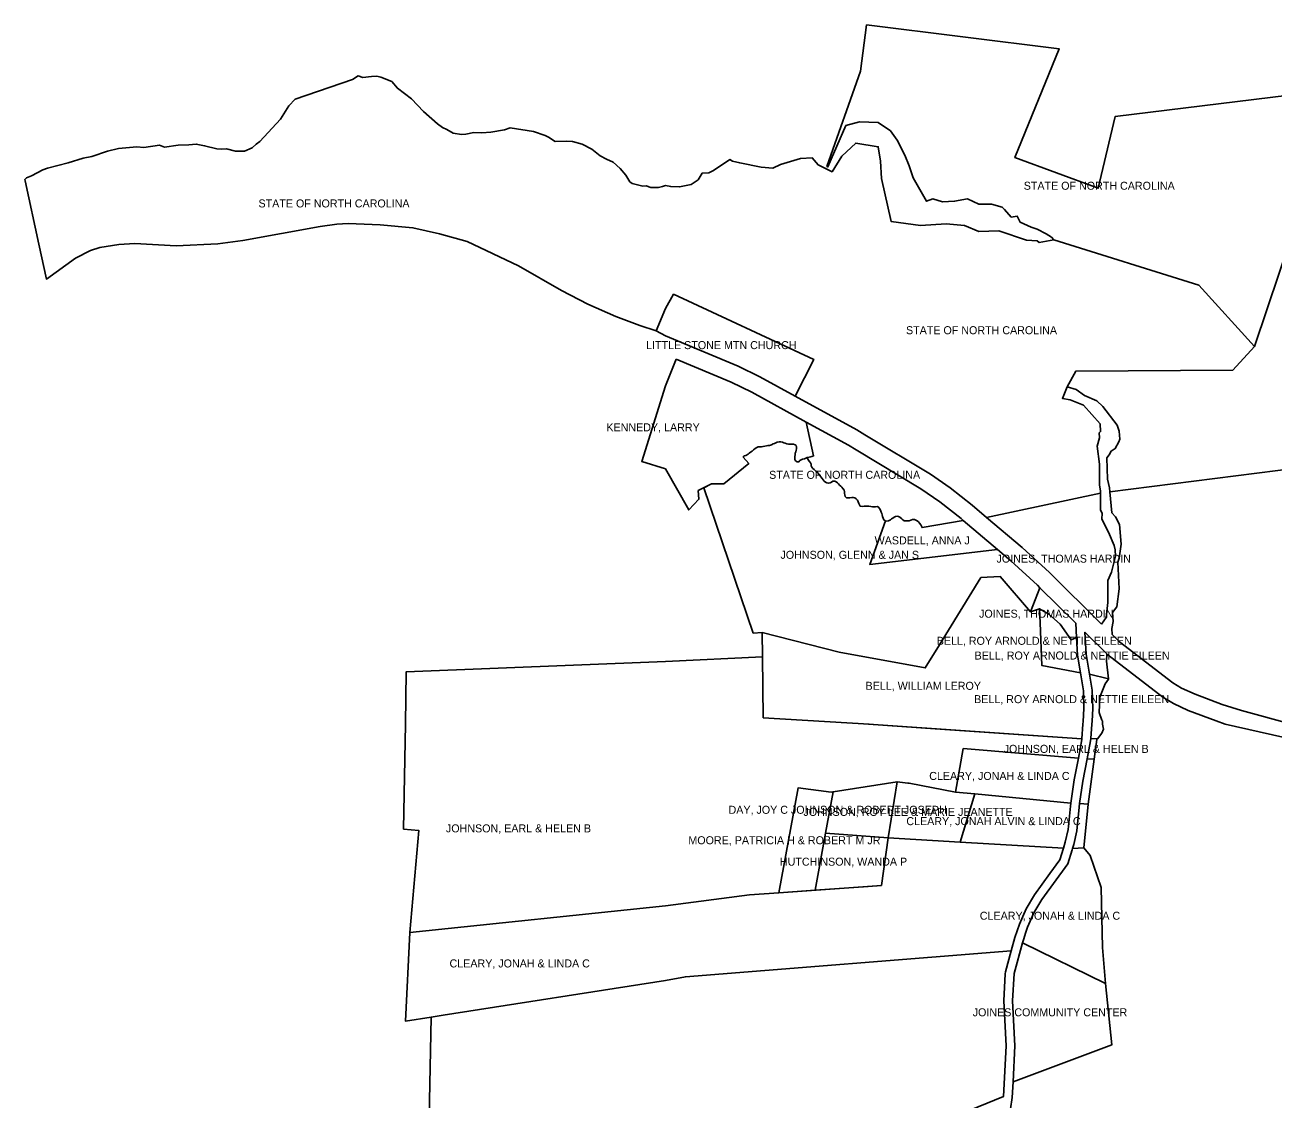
# Model space of a CAD drawing. Extents: x 1387800 to 1395118, y 956481 to 962401.
# Drawn here: x 1387800 to 1392086, y 958713 to 962401 of the extents above; entities that cross this region are included whole.
import ezdxf

# ---------------------------------------------------------------- set-up
doc = ezdxf.new("R2010")
doc.units = 0
doc.layers.add('WILKES_2010PARCELS', color=7, linetype='Continuous')

msp = doc.modelspace()

# ---------------------------------------------------------------- linework, layer by layer
at = {"layer": 'WILKES_2010PARCELS'}
for points in [[(1392319.375, 962181.1875), (1392022, 961296.875), (1391831.25, 961507.75), (1391333.625, 961663.3125), (1391325.375, 961671.8125), (1391307.375, 961683.8125), (1391276.25, 961700.1875), (1391255.375, 961707), (1391217.875, 961723.3125), (1391207.5, 961744), (1391186.75, 961741.4375), (1391163.375, 961767.375), (1391155.625, 961775.125), (1391119.375, 961785.5), (1391075.25, 961785.5), (1391036.375, 961803.625), (1390992.375, 961795.875), (1390950.875, 961793.3125), (1390917.125, 961803.625), (1390896.375, 961795.875), (1390849.75, 961876.25), (1390836.75, 961917.6875), (1390821.25, 961954), (1390795.25, 962005.875), (1390772, 962036.9375), (1390730.5, 962065.5), (1390665.75, 962068.0625), (1390619, 962055.125), (1390557.125, 961913.5), (1390554, 961915.3125), (1390669.625, 962242.375), (1390690, 962400.8125), (1391351.625, 962318.8125), (1391199.75, 961945.5), (1391485.875, 961840.25), (1391544.25, 962086.75), (1392319, 962181.1875)], [(1390000, 961427.125), (1389967.875, 961350.1875), (1389911.375, 961369.125), (1389829.25, 961400), (1389732.625, 961442.5625), (1389642.375, 961489.5), (1389495.125, 961574.1875), (1389318.875, 961657.1875), (1389224.125, 961683.875), (1389132.375, 961704.4375), (1389019.625, 961715.125), (1388910, 961719.1875), (1388871, 961717.125), (1388813.875, 961708.8125), (1388548.125, 961661.0625), (1388462, 961649.875), (1388319.25, 961643.125), (1388177.375, 961650.5), (1388122.625, 961647.4375), (1388057.25, 961637.375), (1388024.625, 961626.4375), (1387974, 961599.8125), (1387874, 961528.6875), (1387848.125, 961648.1875), (1387801.25, 961865.25), (1387800.125, 961870.8125), (1387804.875, 961875.625), (1387822.875, 961883.25), (1387861.25, 961903.25), (1387877.25, 961908.8125), (1387948.5, 961927.625), (1388000.5, 961943.625), (1388029.25, 961949.25), (1388083.75, 961968.0625), (1388120.875, 961976.4375), (1388184.5, 961982.0625), (1388208.125, 961979.625), (1388261.75, 961987.625), (1388279.375, 961981.25), (1388326.5, 961988.0625), (1388362.5, 961988.875), (1388388.5, 961991.625), (1388417, 961986.4375), (1388459, 961975.625), (1388475.75, 961974.0625), (1388492.625, 961975.25), (1388523, 961967.25), (1388554.25, 961967.25), (1388580.625, 961979.25), (1388594.25, 961991.625), (1388606.625, 962000.4375), (1388677.875, 962077.6875), (1388706.25, 962122.875), (1388727.875, 962146.5), (1388925.125, 962213.6875), (1388943.875, 962226.125), (1388960.625, 962220.5), (1388989.875, 962224.125), (1389007.875, 962224.5), (1389022.25, 962221.6875), (1389059.875, 962206.875), (1389079.125, 962183.3125), (1389127.125, 962146.875), (1389168.375, 962103.6875), (1389216.375, 962061.25), (1389234.375, 962048.4375), (1389249.125, 962041.6875), (1389270.75, 962029.25), (1389298.75, 962025.25), (1389313.5, 962026.4375), (1389342, 962031.25), (1389368.75, 962030.875), (1389399.625, 962033.25), (1389446.75, 962040.875), (1389466.75, 962047.6875), (1389546.75, 962035.25), (1389586.375, 962021.25), (1389598.375, 962015.25), (1389620.375, 962000.875), (1389659.625, 962002.0625), (1389680.875, 962000.875), (1389713.625, 961991.25), (1389746.5, 961974.4375), (1389775.625, 961951.625), (1389797.25, 961939.625), (1389820.125, 961929.25), (1389843.625, 961907.625), (1389863.25, 961884.8125), (1389877.25, 961862.8125), (1389884.625, 961856.875), (1389921.875, 961847.4375), (1389932.875, 961848.4375), (1389948.875, 961842.8125), (1389975.75, 961842.875), (1389989.875, 961846.375), (1390000, 961849.6875)], [(1392534.625, 960925.9375), (1391525.125, 960797.5), (1391524.625, 960811.875), (1391517.125, 960841.875), (1391514.625, 960914.75), (1391523.5, 960924.75), (1391529.5, 960937.9375), (1391543.875, 960946.3125), (1391556.25, 960969.5625), (1391559.875, 960978.75), (1391557.5, 961005.9375), (1391550.25, 961026.75), (1391501.125, 961091.5625), (1391480.625, 961110), (1391439, 961128.375), (1391409.875, 961149.625), (1391379, 961158.125), (1391408.625, 961212), (1391947.625, 961215.25), (1392022, 961296.875), (1392319.375, 962181.1875)], [(1390000, 961849.6875), (1390017.75, 961845.875), (1390047.75, 961844.625), (1390087.75, 961853.4375), (1390111.75, 961868.625), (1390125.375, 961891.875), (1390148.625, 961892.6875), (1390164.625, 961901.4375), (1390220.125, 961938.6875), (1390229.375, 961933.0625), (1390254.375, 961927.5), (1390328, 961912.75), (1390367.75, 961909.375), (1390394.875, 961921.8125), (1390462.875, 961942.1875), (1390503.625, 961944.5), (1390523.875, 961920.6875), (1390571.625, 961896.9375), (1390605.5, 961950.125), (1390653.125, 961995.4375), (1390730.5, 961982.5), (1390738.25, 961933.25), (1390740.875, 961873.625), (1390774.625, 961725.875), (1390875.625, 961712.9375), (1390963.875, 961718.125), (1391026, 961712.9375), (1391075.25, 961692.1875), (1391144.125, 961694.625), (1391239, 961662.5625), (1391275.75, 961659.8125), (1391282.875, 961654.125), (1391333.625, 961663.3125), (1391831.25, 961507.75), (1392022, 961296.875), (1391947.625, 961215.25), (1391408.625, 961212), (1391379, 961158.125), (1391362.375, 961118.9375), (1391389.5, 961114), (1391434.625, 961096), (1391492.625, 961031.1875), (1391493.5, 961004.75), (1391488.625, 961000.375), (1391489.5, 960983.9375), (1391482.25, 960954.3125), (1391489.5, 960892.6875), (1391489.875, 960821.875), (1391493.875, 960800.3125), (1391493.875, 960793.3125), (1391102.5, 960710.3125), (1391052.5, 960752.75), (1390977.125, 960811.6875), (1390909.625, 960859.0625), (1390684, 960993.8125), (1390656.125, 961010.9375), (1390444.75, 961126.9375), (1390508.75, 961252.8125), (1390027.375, 961476.5), (1390000, 961427.125)], [(1390000, 961427.125), (1390027.375, 961476.5), (1390508.75, 961252.8125), (1390444.75, 961126.9375), (1390323.875, 961193.1875), (1390249.375, 961229.3125), (1390000, 961333.6875)], [(1390000, 961333.6875), (1389967.875, 961350.1875), (1390000, 961427.125)], [(1390035.875, 961253.5), (1390224.625, 961174.5625), (1390296.375, 961139.8125), (1390483.25, 961037.375), (1390508.25, 960921.0625), (1390502.625, 960919.875), (1390497.75, 960917.875), (1390492.625, 960916.6875), (1390486.625, 960915.5625), (1390486.125, 960915.4375), (1390481.375, 960913.875), (1390476.5, 960911.875), (1390470.125, 960910.25), (1390465.375, 960907.875), (1390460.875, 960905.4375), (1390457.75, 960901.4375), (1390451.375, 960901.4375), (1390446.5, 960904.25), (1390443.375, 960908.625), (1390443.375, 960913.875), (1390443.75, 960919.0625), (1390444.5, 960925.0625), (1390445.375, 960931.0625), (1390447.75, 960935.5), (1390448.875, 960940.6875), (1390449.375, 960945.875), (1390449.375, 960951.125), (1390448.875, 960956.6875), (1390444.875, 960959.9375), (1390439.25, 960961.5), (1390428.5, 960961.5), (1390422.875, 960961.125), (1390416.125, 960962.3125), (1390410.875, 960964.6875), (1390405.625, 960966.3125), (1390400.875, 960968.75), (1390395.25, 960969.9375), (1390390, 960969.9375), (1390383.625, 960968.75), (1390378.5, 960966.6875), (1390374, 960964.3125), (1390368.875, 960962.3125), (1390363.625, 960959.9375), (1390357.25, 960957.5), (1390351.25, 960956.6875), (1390346, 960955.5), (1390340.375, 960954.6875), (1390334.375, 960953.125), (1390329.125, 960952.6875), (1390323.125, 960952.6875), (1390318, 960952.3125), (1390313.125, 960949.875), (1390307.125, 960947.125), (1390301.5, 960941.875), (1390297.125, 960937.875), (1390291.5, 960934.25), (1390287.5, 960931.0625), (1390283.125, 960927.5), (1390275.875, 960923.0625), (1390269.875, 960921.0625), (1390266.375, 960917.4375), (1390285.5, 960895.0625), (1390200.25, 960825.375), (1390157.375, 960824.9375), (1390111.75, 960802.125), (1390114.125, 960772.5), (1390079.75, 960736.0625), (1390079.625, 960735.875), (1390000, 960876.875)], [(1390000, 961161.4375), (1390035.875, 961253.5)], [(1390000, 960877.5625), (1389918.125, 960902.625), (1390000, 961161.4375)], [(1392149.75, 960000), (1391977.375, 960046.8125), (1391911.125, 960068), (1391818.25, 960103.375), (1391771.875, 960124.25), (1391741.25, 960142.6875), (1391558.375, 960283.5625), (1391533.875, 960307.6875), (1391532.75, 960328.5), (1391536.75, 960353.3125), (1391534.75, 960384.125), (1391549.125, 960403.75), (1391557.125, 960464.9375), (1391553.125, 960557), (1391557.5, 960570.1875), (1391563.875, 960618.625), (1391559.125, 960686.25), (1391544.75, 960712.25), (1391532.75, 960726.25), (1391525.125, 960797.5), (1392534.625, 960925.9375)], [(1390335.125, 960021.75), (1390332.875, 960231.1875), (1390331.25, 960314.75), (1390596.25, 960247.125), (1390891.875, 960193.8125), (1390940.25, 960272.375), (1391082.5, 960503.8125), (1391149.375, 960507), (1391252.625, 960386.4375), (1391284.25, 960396.9375), (1391286, 960348.125), (1391291.375, 960202.0625), (1391424.75, 960176.3125), (1391434.75, 960114.75), (1391436.5, 960054.625), (1391434.25, 960010.0625), (1391433, 960000)], [(1390000, 960215.75), (1390332.875, 960231.1875), (1390335.125, 960021.75)], [(1391500.5, 960000), (1391500.5, 960011.5), (1391498, 960014.4375), (1391489.125, 960040.4375), (1391491.5, 960092.8125), (1391509.5, 960139.25), (1391521.125, 960154.4375), (1391520.875, 960156.1875), (1391513.5, 960216.5), (1391515.375, 960241.75), (1391518.875, 960238.3125), (1391707.125, 960093.0625), (1391743.75, 960071), (1391795, 960047.875), (1391890.75, 960011.375), (1391921.5, 960000)], [(1389106.5, 960000), (1389109.125, 960179.75), (1390000, 960215.625)], [(1391463.125, 960000), (1391464.25, 960010.6875), (1391466.5, 960054.25), (1391464.75, 960117.625), (1391455.75, 960172.5625), (1391520.875, 960156.1875), (1391521.125, 960154.4375), (1391509.5, 960139.25), (1391491.5, 960092.8125), (1391489.125, 960040.4375), (1391498, 960014.4375), (1391500.5, 960011.5), (1391500.5, 960000)], [(1390698.5, 959999.875), (1390335.125, 960021.75)], [(1390000, 959376.75), (1389121.375, 959285.375), (1389153.125, 959634.8125), (1389100.5, 959640.1875), (1389106.5, 960000)], [(1390696.25, 960000), (1391429.75, 959949.75), (1391429.625, 959947.5625), (1391417.375, 959884.25), (1391022.125, 959916.5625), (1390995, 959767.25), (1390836.375, 959797.4375), (1390831.375, 959798.375), (1390795.125, 959802.6875), (1390574.875, 959768.25), (1390568.125, 959767.125), (1390455.625, 959782), (1390388.875, 959421.8125), (1390288, 959414.625), (1390000, 959376.4375)], [(1390696.25, 960000), (1390698, 960000)], [(1391433, 960000), (1391429.75, 959949.75), (1390926.125, 959984.25), (1390696.25, 960000)], [(1391184.5, 958679.5), (1391190.625, 958718.25), (1391193.375, 958772.6875), (1391532, 958899.375), (1391510.125, 959109.9375), (1391500.125, 959234.0625), (1391496.125, 959439.875), (1391457.375, 959550), (1391436.5, 959575.625), (1391451.375, 959725.75), (1391472, 959879.8125), (1391481, 959947.5625), (1391482.875, 959950), (1391497.75, 959969.9375), (1391503.75, 959982.75), (1391500.5, 960000)], [(1391500.5, 960000), (1391503.75, 959982.75), (1391497.75, 959969.9375), (1391482.875, 959950), (1391459.875, 959951.5), (1391463.125, 960000)], [(1391921.5, 960000), (1392119.375, 959955.625)], [(1390000, 959376.4375), (1390288, 959414.625), (1390388.875, 959421.8125), (1390741, 959446.8125), (1390764.5, 959610.25), (1391011, 959595.875), (1391365.875, 959574.1875), (1391353.5, 959535), (1391319, 959487.3125), (1391266.625, 959415.0625), (1391237.625, 959366.5), (1391214.75, 959314), (1391199.75, 959268.4375), (1391187, 959222.5625), (1390068, 959133.1875), (1390000, 959120.375)], [(1390000, 959120.3125), (1389236.75, 959001.5625), (1389195.125, 958995), (1389106.5, 958981.3125), (1389121.375, 959285.375), (1390000, 959376.75)], [(1390000, 959120.375), (1390068, 959133.1875), (1391187, 959222.5625), (1391166.625, 959149.625), (1391166.25, 959143.375), (1391161.25, 959050.1875), (1391169.625, 958896.4375), (1391160.625, 958722.1875), (1390352, 958392.9375), (1390000, 958040.8125)], [(1390000, 958040.8125), (1389867.875, 957908.625), (1389706.875, 957904.5), (1389181.75, 958306.5), (1389195.125, 958995), (1389236.75, 959001.5625), (1390000, 959120.3125)]]:
    msp.add_lwpolyline(points, dxfattribs=at)
for points in [[(1390617.125, 960782.125), (1390615.875, 960787.3125), (1390614.75, 960792.5), (1390614.75, 960798.9375), (1390612.75, 960803.75), (1390609.125, 960809.75), (1390605.5, 960814.125), (1390601.875, 960817.75), (1390597.5, 960820.9375), (1390593.875, 960824.9375), (1390590.625, 960828.9375), (1390585.875, 960832.1875), (1390580.625, 960834.5625), (1390573.875, 960834.9375), (1390570.25, 960831.375), (1390565.5, 960828.9375), (1390560.25, 960827.75), (1390553.875, 960828.9375), (1390548.625, 960831.75), (1390544.625, 960834.9375), (1390541.375, 960839), (1390537.875, 960843.75), (1390532.625, 960849.8125), (1390529.375, 960854.1875), (1390525.75, 960858.5625), (1390522.25, 960863.8125), (1390515.375, 960869.375), (1390509.75, 960874.1875), (1390505.375, 960878.1875), (1390501.75, 960882.25), (1390500.125, 960887), (1390499.75, 960892.625), (1390497.375, 960897.4375), (1390494.125, 960902.625), (1390490.125, 960907.4375), (1390487, 960913.875), (1390486.625, 960915.5625), (1390492.625, 960916.6875), (1390497.75, 960917.875), (1390502.625, 960919.875), (1390508.25, 960921.0625), (1390483.25, 961037.375), (1390627.75, 960958.1875), (1390654.5, 960942.125), (1390876.875, 960808.6875), (1390941.375, 960763.4375), (1391014.5, 960706.25), (1391022.375, 960699.625), (1390880.625, 960675.5625), (1390879, 960680.375), (1390876.25, 960685.1875), (1390872.25, 960690.8125), (1390868.25, 960695.1875), (1390864.25, 960698.4375), (1390859.75, 960701.1875), (1390854.625, 960703.625), (1390847.375, 960702.8125), (1390841.75, 960700.4375), (1390836.625, 960698.8125), (1390825, 960698.8125), (1390819, 960698.4375), (1390815, 960701.625), (1390811.75, 960705.625), (1390804.875, 960711.625), (1390800.125, 960713.25), (1390794.875, 960714), (1390789.75, 960713.625), (1390784.875, 960711.25), (1390780.5, 960707.25), (1390776.125, 960704.8125), (1390771.75, 960702), (1390765.25, 960698.8125), (1390759.25, 960697.625), (1390755.625, 960698.375), (1390753.625, 960698.8125), (1390749.25, 960702.4375), (1390746.875, 960707.625), (1390744.875, 960712.8125), (1390743.625, 960718.8125), (1390742.5, 960724.0625), (1390740, 960728.4375), (1390737.625, 960734.875), (1390734.875, 960740.875), (1390731.25, 960745.6875), (1390726.5, 960747.25), (1390720.875, 960746.875), (1390715.625, 960746.4375), (1390710.375, 960746.875), (1390705.25, 960747.25), (1390698.375, 960748.4375), (1390693.25, 960749.25), (1390687.25, 960748.875), (1390682, 960748.4375), (1390676.75, 960748.0625), (1390668, 960748.875), (1390666.375, 960753.6875), (1390664, 960758.5), (1390661.625, 960763.6875), (1390658.75, 960768.875), (1390654.375, 960774.125), (1390650, 960776.875), (1390645.125, 960778.5), (1390639.5, 960778.5), (1390633.125, 960777.6875), (1390626.375, 960777.3125), (1390620.75, 960777.6875)], [(1390331.25, 960314.75), (1390300.75, 960313.25), (1390131.25, 960811.875), (1390157.375, 960824.9375), (1390200.25, 960825.375), (1390285.5, 960895.0625), (1390266.375, 960917.4375), (1390269.875, 960921.0625), (1390275.875, 960923.0625), (1390283.125, 960927.5), (1390287.5, 960931.0625), (1390291.5, 960934.25), (1390297.125, 960937.875), (1390301.5, 960941.875), (1390307.125, 960947.125), (1390313.125, 960949.875), (1390318, 960952.3125), (1390323.125, 960952.6875), (1390329.125, 960952.6875), (1390334.375, 960953.125), (1390340.375, 960954.6875), (1390346, 960955.5), (1390351.25, 960956.6875), (1390357.25, 960957.5), (1390363.625, 960959.9375), (1390368.875, 960962.3125), (1390374, 960964.3125), (1390378.5, 960966.6875), (1390383.625, 960968.75), (1390390, 960969.9375), (1390395.25, 960969.9375), (1390400.875, 960968.75), (1390405.625, 960966.3125), (1390410.875, 960964.6875), (1390416.125, 960962.3125), (1390422.875, 960961.125), (1390428.5, 960961.5), (1390439.25, 960961.5), (1390444.875, 960959.9375), (1390448.875, 960956.6875), (1390449.375, 960951.125), (1390449.375, 960945.875), (1390448.875, 960940.6875), (1390447.75, 960935.5), (1390445.375, 960931.0625), (1390444.5, 960925.0625), (1390443.75, 960919.0625), (1390443.375, 960913.875), (1390443.375, 960908.625), (1390446.5, 960904.25), (1390451.375, 960901.4375), (1390457.75, 960901.4375), (1390460.875, 960905.4375), (1390465.375, 960907.875), (1390470.125, 960910.25), (1390476.5, 960911.875), (1390481.375, 960913.875), (1390486.125, 960915.4375), (1390486.625, 960915.5625), (1390487, 960913.875), (1390490.125, 960907.4375), (1390494.125, 960902.625), (1390497.375, 960897.4375), (1390499.75, 960892.625), (1390500.125, 960887), (1390501.75, 960882.25), (1390505.375, 960878.1875), (1390509.75, 960874.1875), (1390515.375, 960869.375), (1390522.25, 960863.8125), (1390525.75, 960858.5625), (1390529.375, 960854.1875), (1390532.625, 960849.8125), (1390537.875, 960843.75), (1390541.375, 960839), (1390544.625, 960834.9375), (1390548.625, 960831.75), (1390553.875, 960828.9375), (1390560.25, 960827.75), (1390565.5, 960828.9375), (1390570.25, 960831.375), (1390573.875, 960834.9375), (1390580.625, 960834.5625), (1390585.875, 960832.1875), (1390590.625, 960828.9375), (1390593.875, 960824.9375), (1390597.5, 960820.9375), (1390601.875, 960817.75), (1390605.5, 960814.125), (1390609.125, 960809.75), (1390612.75, 960803.75), (1390614.75, 960798.9375), (1390614.75, 960792.5), (1390615.875, 960787.3125), (1390617.125, 960782.125), (1390620.75, 960777.6875), (1390626.375, 960777.3125), (1390633.125, 960777.6875), (1390639.5, 960778.5), (1390645.125, 960778.5), (1390650, 960776.875), (1390654.375, 960774.125), (1390658.75, 960768.875), (1390661.625, 960763.6875), (1390664, 960758.5), (1390666.375, 960753.6875), (1390668, 960748.875), (1390676.75, 960748.0625), (1390682, 960748.4375), (1390687.25, 960748.875), (1390693.25, 960749.25), (1390698.375, 960748.4375), (1390705.25, 960747.25), (1390710.375, 960746.875), (1390715.625, 960746.4375), (1390720.875, 960746.875), (1390726.5, 960747.25), (1390731.25, 960745.6875), (1390734.875, 960740.875), (1390737.625, 960734.875), (1390740, 960728.4375), (1390742.5, 960724.0625), (1390743.625, 960718.8125), (1390744.875, 960712.8125), (1390746.875, 960707.625), (1390749.25, 960702.4375), (1390753.625, 960698.8125), (1390755.625, 960698.375), (1390701.125, 960548.75), (1391139.875, 960599.9375), (1391185, 960561.5625), (1391276.875, 960477.0625), (1391285.25, 960468.875), (1391252.625, 960386.4375), (1391149.375, 960507), (1391082.5, 960503.8125), (1390940.25, 960272.375), (1390891.875, 960193.8125), (1390596.25, 960247.125)], [(1391497, 960344.1875), (1391318.375, 960520.5625), (1391224.75, 960606.5625), (1391102.5, 960710.3125), (1391493.875, 960793.3125), (1391493.5, 960735.0625), (1391499.125, 960725.0625), (1391497.5, 960704.25), (1391521.125, 960659.4375), (1391539.875, 960613.8125), (1391544.25, 960599.4375), (1391544.75, 960577), (1391531.5, 960521.8125), (1391518.25, 960494.1875), (1391518.25, 960417.75), (1391513.125, 960366.125)], [(1390701.125, 960548.75), (1390755.625, 960698.375), (1390759.25, 960697.625), (1390765.25, 960698.8125), (1390771.75, 960702), (1390776.125, 960704.8125), (1390780.5, 960707.25), (1390784.875, 960711.25), (1390789.75, 960713.625), (1390794.875, 960714), (1390800.125, 960713.25), (1390804.875, 960711.625), (1390811.75, 960705.625), (1390815, 960701.625), (1390819, 960698.4375), (1390825, 960698.8125), (1390836.625, 960698.8125), (1390841.75, 960700.4375), (1390847.375, 960702.8125), (1390854.625, 960703.625), (1390859.75, 960701.1875), (1390864.25, 960698.4375), (1390868.25, 960695.1875), (1390872.25, 960690.8125), (1390876.25, 960685.1875), (1390879, 960680.375), (1390880.625, 960675.5625), (1391022.375, 960699.625), (1391139.875, 960599.9375)], [(1391252.625, 960386.4375), (1391285.25, 960468.875), (1391408.125, 960347.625), (1391411.25, 960297.625), (1391392.625, 960290.5), (1391355, 960343.75), (1391316.25, 960377.75), (1391284.25, 960396.9375)], [(1391291.375, 960202.0625), (1391286, 960348.125), (1391284.25, 960396.9375), (1391316.25, 960377.75), (1391355, 960343.75), (1391392.625, 960290.5), (1391411.25, 960297.625), (1391414.875, 960237.6875), (1391424.75, 960176.3125)], [(1391455.75, 960172.5625), (1391444.625, 960241.0625), (1391440.125, 960316.0625), (1391515.375, 960241.75), (1391513.5, 960216.5), (1391520.875, 960156.1875)], [(1391447.375, 959881.8125), (1391459.375, 959943.6875), (1391459.875, 959951.5), (1391482.875, 959950), (1391481, 959947.5625), (1391472, 959879.8125)], [(1390995, 959767.25), (1391022.125, 959916.5625), (1391417.375, 959884.25), (1391403, 959809.875), (1391391.5, 959728.8125), (1391061.5, 959760.8125)], [(1391421.5, 959727.625), (1391432.5, 959804.875), (1391447.375, 959881.8125), (1391472, 959879.8125), (1391451.375, 959725.75)], [(1390549.25, 959626), (1390574.875, 959768.25), (1390795.125, 959802.6875), (1390764.5, 959610.25), (1390764.25, 959610.3125)], [(1390764.5, 959610.25), (1390795.125, 959802.6875), (1390831.375, 959798.375), (1390836.375, 959797.4375), (1390995, 959767.25), (1391061.5, 959760.8125), (1391011, 959595.875)], [(1390388.875, 959421.8125), (1390455.625, 959782), (1390568.125, 959767.125), (1390574.875, 959768.25), (1390549.25, 959626), (1390513.875, 959430.6875)], [(1391011, 959595.875), (1391061.5, 959760.8125), (1391391.5, 959728.8125), (1391390.125, 959719.25), (1391382.875, 959638.875), (1391372.625, 959595.5), (1391365.875, 959574.1875)], [(1391397.125, 959573.0625), (1391401.625, 959587.5), (1391412.625, 959634.125), (1391419.875, 959715.75), (1391421.5, 959727.625), (1391451.375, 959725.75), (1391436.5, 959575.625)], [(1390513.875, 959430.6875), (1390549.25, 959626), (1390764.25, 959610.3125), (1390764.5, 959610.25), (1390741, 959446.8125), (1390696.125, 959443.625)], [(1391237.125, 959286.0625), (1391242.75, 959303.25), (1391264.375, 959352.75), (1391291.625, 959398.5625), (1391380.75, 959521.375), (1391395.625, 959568.5), (1391397.125, 959573.0625), (1391436.5, 959575.625), (1391457.375, 959550), (1391496.125, 959439.875), (1391500.125, 959234.0625), (1391510.125, 959109.9375), (1391225.75, 959249.875), (1391228.5, 959259.6875)], [(1391193.375, 958772.6875), (1391199.625, 958896.4375), (1391191.25, 959050.1875), (1391196.375, 959144.75), (1391225.75, 959249.875), (1391510.125, 959109.9375), (1391532, 958899.375)]]:
    msp.add_lwpolyline(points, close=True, dxfattribs=at)

# ---------------------------------------------------------------- texts
for s, p in [('STATE OF NORTH CAROLINA', (1391229.760538, 961835.103254)), ('STATE OF NORTH CAROLINA', (1388602.078183, 961774.415754)), ('STATE OF NORTH CAROLINA', (1390825.508984, 961339.134504)), ('LITTLE STONE MTN CHURCH', (1389933.071066, 961287.978254)), ('KENNEDY, LARRY', (1389796.632597, 961005.759504)), ('STATE OF NORTH CAROLINA', (1390355.494855, 960842.728254)), ('WASDELL, ANNA J', (1390717.783206, 960617.634504)), ('JOHNSON, GLENN & JAN S', (1390394.434314, 960568.134504)), ('JOINES, THOMAS HARDIN', (1391136.402485, 960555.009504)), ('JOINES, THOMAS HARDIN', (1391076.386091, 960365.947004)), ('BELL, ROY ARNOLD & NETTIE EILEEN', (1390931.004089, 960272.884504)), ('BELL, ROY ARNOLD & NETTIE EILEEN', (1391061.10697, 960222.384504)), ('BELL, WILLIAM LEROY', (1390686.689103, 960118.323341)), ('BELL, ROY ARNOLD & NETTIE EILEEN', (1391059.324543, 960072.540754)), ('JOHNSON, EARL & HELEN B', (1391160.769089, 959901.915754)), ('CLEARY, JONAH & LINDA C', (1390905.272907, 959808.947004)), ('DAY, JOY C JOHNSON & ROBERT JOSEPH', (1390216.052644, 959692.728254)), ('JOHNSON, ROY LEE & MARIE JEANETTE', (1390473.258828, 959685.540754)), ('CLEARY, JONAH ALVIN & LINDA C', (1390826.749662, 959653.759504)), ('JOHNSON, EARL & HELEN B', (1389245.68985, 959628.947004)), ('MOORE, PATRICIA H & ROBERT M JR', (1390078.223438, 959588.165754)), ('HUTCHINSON, WANDA P', (1390392.523759, 959514.603254)), ('CLEARY, JONAH & LINDA C', (1391079.01517, 959329.040754)), ('CLEARY, JONAH & LINDA C', (1389258.085457, 959165.290754)), ('JOINES COMMUNITY CENTER', (1391054.580849, 958997.540754))]:
    msp.add_text(s, height=27.480992, dxfattribs=at).set_placement(p)

doc.saveas('drawing.dxf')
